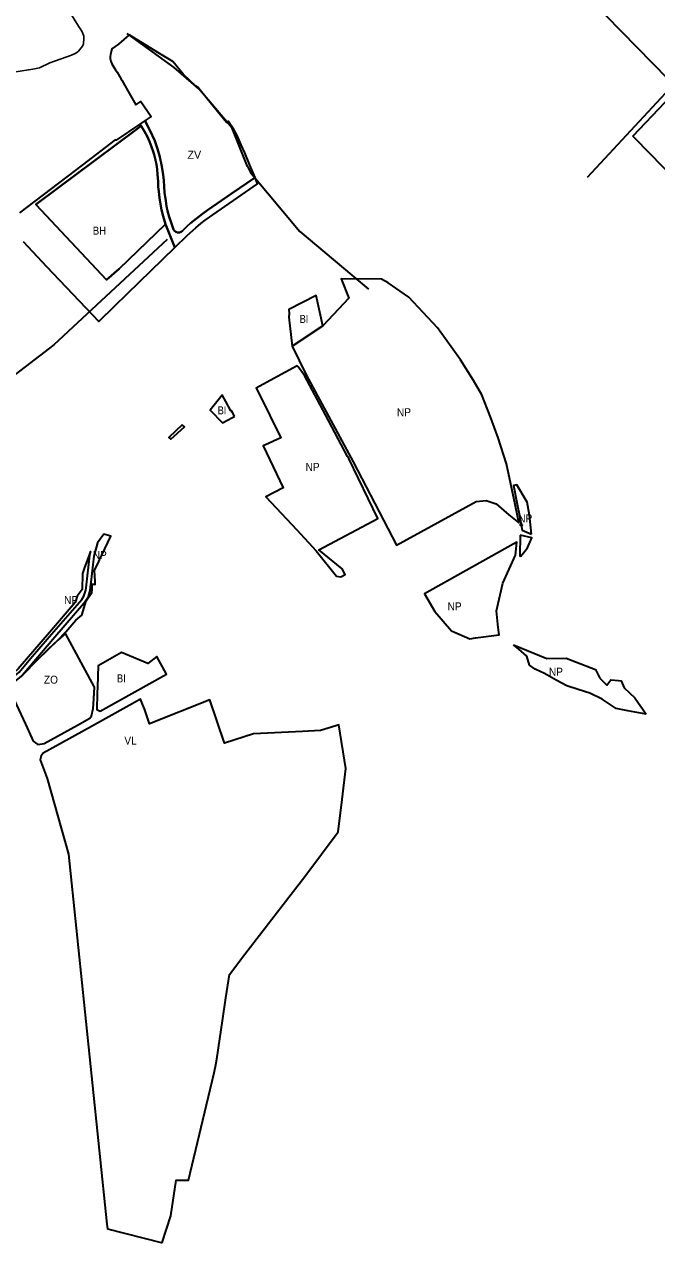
# Model space of a CAD drawing. Extents: x -650276 to -642489, y -1074311 to -1066720.
# Drawn here: x -646730 to -645782, y -1073849 to -1072023 of the extents above; entities that cross this region are included whole.
import ezdxf

# ---------------------------------------------------------------- set-up
doc = ezdxf.new("R2010")
doc.units = 0
doc.header["$LTSCALE"] = 4.8
doc.header["$PDMODE"] = 32
doc.header["$PDSIZE"] = 2.4
for name, color, linetype, lineweight in [('1', 7, 'Continuous', 35), ('15', 7, 'Continuous', 35), ('2', 7, 'Continuous', 35), ('34', 7, 'Continuous', 35), ('40', 7, 'Continuous', 35), ('42', 7, 'Continuous', 35), ('48', 7, 'Continuous', 35), ('54', 7, 'Continuous', 35), ('61', 7, 'Continuous', 25)]:
    doc.layers.add(name, color=color, linetype=linetype, lineweight=lineweight)
doc.layers.add('62', color=7, linetype='Continuous')

msp = doc.modelspace()

# ---------------------------------------------------------------- linework, layer by layer
at = {"layer": '1'}
msp.add_lwpolyline([(-646606.848, -1072405.785), (-646587.666, -1072389.082), (-646518.208, -1072321.92), (-646519.417, -1072318.408), (-646522.007, -1072309.932), (-646524.282, -1072300.849), (-646526, -1072292.201), (-646527.5, -1072282.657), (-646528.566, -1072273.308), (-646529.182, -1072265.941), (-646529.607, -1072258.124), (-646530.188, -1072247.442), (-646530.892, -1072239.747), (-646531.93, -1072232.861), (-646533.286, -1072226.031), (-646535.344, -1072217.844), (-646536.772, -1072213.218), (-646539.168, -1072206.122), (-646539.168, -1072206.122), (-646542.484, -1072197.985), (-646546.09, -1072190.428), (-646549.793, -1072183.38), (-646554.56, -1072175.629), (-646555.051, -1072174.933), (-646563.299, -1072181.091), (-646710.684, -1072291.133), (-646712.634, -1072292.59)], close=True, dxfattribs=at)
at = {"layer": '15'}
msp.add_lwpolyline([(-646529.182, -1072265.941), (-646528.566, -1072273.308), (-646527.5, -1072282.657), (-646526, -1072292.201), (-646524.282, -1072300.849), (-646522.007, -1072309.932), (-646519.417, -1072318.408), (-646518.208, -1072321.92), (-646504.244, -1072357.026), (-646485.656, -1072338.908), (-646473.069, -1072327.765), (-646465.227, -1072321.127), (-646459.03, -1072316.137), (-646380.12, -1072261.44), (-646384.056, -1072252.138), (-646420.085, -1072276.737), (-646455.557, -1072301.131), (-646462.79, -1072306.784), (-646480.923, -1072320.667), (-646486.273, -1072325.526), (-646492.813, -1072332.07), (-646494.794, -1072333.558), (-646497.569, -1072334.55), (-646500.244, -1072334.45), (-646503.018, -1072333.459), (-646504.802, -1072331.971), (-646506.189, -1072329.889), (-646509.954, -1072319.377), (-646512.729, -1072311.048), (-646515.305, -1072301.925), (-646516.692, -1072294.983), (-646518.079, -1072287.051), (-646519.756, -1072274.861), (-646521.051, -1072256.707), (-646521.646, -1072248.378), (-646523.628, -1072235.883), (-646526.798, -1072221.011), (-646530.167, -1072209.31), (-646534.527, -1072197.411), (-646541.822, -1072181.102), (-646547.606, -1072170.835), (-646548.676, -1072166.737), (-646556.693, -1072172.16), (-646555.051, -1072174.933), (-646554.56, -1072175.629), (-646549.793, -1072183.38), (-646546.09, -1072190.428), (-646542.484, -1072197.985), (-646539.168, -1072206.122), (-646536.772, -1072213.218), (-646535.344, -1072217.844), (-646533.286, -1072226.031), (-646531.93, -1072232.861), (-646530.892, -1072239.747), (-646530.188, -1072247.442), (-646529.607, -1072258.124)], close=True, dxfattribs=at)
at = {"layer": '2'}
msp.add_line((-646417.787, -1072612.168), (-646414.77, -1072610.61), dxfattribs=at)
for points in [[(-645817.219, -1072189.975), (-645768.649, -1072139.283), (-645740.45, -1072168.23), (-645559.34, -1072354.42), (-645546.82, -1072365.72), (-645550.41, -1072368.47), (-645636.37, -1072379.57), (-645650.78, -1072342.73), (-645674, -1072338), (-645789.298, -1072218.833)], [(-646333.34, -1072461.67), (-646328.45, -1072504.81), (-646282.47, -1072474.34), (-646292.44, -1072428.89), (-646333.33, -1072450.12), (-646332.68, -1072456.19)], [(-646620.38, -1073015.9), (-646620.71, -1073025.49), (-646621.44, -1073049.79), (-646616.55, -1073052.21), (-646516.7, -1072996.65), (-646531.46, -1072970.12), (-646544.68, -1072980.62), (-646584.23, -1072964.22), (-646619.48, -1072984.34)]]:
    msp.add_lwpolyline(points, close=True, dxfattribs=at)
for points in [[(-646420.36, -1072601.78), (-646427.95, -1072588.07), (-646432.57, -1072579.75), (-646433.36, -1072578.45), (-646451.458, -1072601.008), (-646433.024, -1072620.04), (-646417.787, -1072612.168)], [(-646414.77, -1072610.61), (-646419.11, -1072602.03), (-646419.47, -1072601.31), (-646419.02, -1072604.18), (-646420.36, -1072601.78)]]:
    msp.add_lwpolyline(points, dxfattribs=at)
at = {"layer": '34'}
msp.add_lwpolyline([(-646663.83, -1073266.33), (-646606.251, -1073821.086), (-646605.36, -1073828.11), (-646525.12, -1073848.38), (-646523.34, -1073848.83), (-646510.62, -1073808.79), (-646502.13, -1073755.15), (-646483.76, -1073755.02), (-646446.04, -1073596.49), (-646443.21, -1073584.6), (-646441.43, -1073573.76), (-646436.91, -1073543.35), (-646432.87, -1073516.19), (-646427.79, -1073482.07), (-646422.54, -1073446.74), (-646399.55, -1073416.41), (-646350.34, -1073353.07), (-646309.38, -1073299.93), (-646259.2, -1073233.16), (-646253.35, -1073184.6), (-646247.76, -1073138.19), (-646258.14, -1073072.71), (-646262.94, -1073074.15), (-646285.77, -1073081.01), (-646312.87, -1073082.4), (-646386.27, -1073086.15), (-646430.02, -1073100.1), (-646452.08, -1073034.96), (-646542.62, -1073071.1), (-646550.01, -1073048.55), (-646552.79, -1073041.53), (-646555.79, -1073033.92), (-646624.69, -1073072.66), (-646691.76, -1073109.71), (-646701.78, -1073114.9), (-646704.98, -1073119), (-646706.23, -1073125.02), (-646695.77, -1073153.13)], close=True, dxfattribs=at)
at = {"layer": '40'}
msp.add_lwpolyline([(-646507.28, -1072078.4), (-646530.073, -1072064.559), (-646573.05, -1072038.46), (-646588.75, -1072052.06), (-646598.827, -1072059.244), (-646599.86, -1072063.71), (-646601, -1072067.55), (-646601.42, -1072071.01), (-646601.16, -1072074.07), (-646600.8, -1072075.94), (-646600.22, -1072077.86), (-646598.67, -1072081.55), (-646595.86, -1072086.82), (-646593.13, -1072091.01), (-646591.02, -1072094.4), (-646585.08, -1072104.81), (-646583.9, -1072106.42), (-646577.41, -1072117.76), (-646577.08, -1072118.7), (-646563.11, -1072143.03), (-646555.49, -1072138.17), (-646539.94, -1072160.83), (-646548.676, -1072166.737), (-646547.606, -1072170.835), (-646541.822, -1072181.102), (-646534.527, -1072197.411), (-646530.167, -1072209.31), (-646526.798, -1072221.011), (-646523.628, -1072235.883), (-646521.646, -1072248.378), (-646521.051, -1072256.707), (-646519.756, -1072274.861), (-646518.079, -1072287.051), (-646516.692, -1072294.983), (-646515.305, -1072301.925), (-646512.729, -1072311.048), (-646509.954, -1072319.377), (-646506.189, -1072329.889), (-646504.802, -1072331.971), (-646503.018, -1072333.459), (-646500.244, -1072334.45), (-646497.569, -1072334.55), (-646494.794, -1072333.558), (-646492.813, -1072332.07), (-646486.273, -1072325.526), (-646480.923, -1072320.667), (-646462.79, -1072306.784), (-646455.557, -1072301.131), (-646420.085, -1072276.737), (-646384.056, -1072252.138), (-646391.77, -1072233.91), (-646399.6, -1072215.39), (-646404.67, -1072203.42), (-646410.68, -1072189.36), (-646415.84, -1072180.43), (-646424.56, -1072167.96), (-646426.98, -1072169.74), (-646455.75, -1072134.29), (-646468.35, -1072118.76), (-646469.41, -1072117.44), (-646472.72, -1072115.38), (-646491.69, -1072097.45)], close=True, dxfattribs=at)
at = {"layer": '42'}
msp.add_lwpolyline([(-646731.82, -1072348.2), (-646696.83, -1072385.81), (-646618.158, -1072468.098), (-646594.606, -1072444.422), (-646575.792, -1072426.789), (-646504.244, -1072357.026), (-646518.208, -1072321.92), (-646587.666, -1072389.082), (-646606.848, -1072405.785), (-646712.634, -1072292.59), (-646563.299, -1072181.091), (-646555.051, -1072174.933), (-646556.693, -1072172.16), (-646592.2, -1072196.17), (-646593.85, -1072195.48), (-646643.55, -1072233.5), (-646737.449, -1072305.019)], dxfattribs=at)
msp.add_lwpolyline([(-646668.53, -1072935.52), (-646680.07, -1072945.74), (-646710.3, -1072975.31), (-646732.95, -1072998.07), (-646744.92, -1073007.46), (-646755.58, -1073013.43), (-646728.25, -1073071.54), (-646719.09, -1073092.43), (-646716.98, -1073097.26), (-646709.88, -1073101.87), (-646700.42, -1073100.42), (-646650.54, -1073072.96), (-646631.82, -1073062.65), (-646629.15, -1073059.18), (-646626.91, -1073048.17), (-646626.55, -1073041.48), (-646625.01, -1073016.38)], close=True, dxfattribs=at)
at = {"layer": '48'}
for points in [[(-646056.42, -1072556.49), (-646075.82, -1072525.54), (-646110.61, -1072477.49), (-646153.49, -1072431.54), (-646172.81, -1072418.2), (-646184.449, -1072410.256), (-646194.19, -1072404.62), (-646254.75, -1072404.25), (-646243.17, -1072432.88), (-646282.47, -1072474.34), (-646328.45, -1072504.81), (-646307.6, -1072547.74), (-646236.97, -1072678.31), (-646171.72, -1072803.51), (-646052.58, -1072737.82), (-646037.23, -1072736.38), (-646022.4, -1072741.58), (-646003.22, -1072757.85), (-645988.43, -1072769.93), (-645990.04, -1072761.78), (-645993.89, -1072742.23), (-646006.66, -1072681.4), (-646019.16, -1072642.35), (-646030.17, -1072612.31), (-646043.87, -1072578.12)], [(-646310.01, -1072549.22), (-646319.56, -1072536.05), (-646320.62, -1072534.6), (-646350.18, -1072550.59), (-646382.41, -1072568.01), (-646377.84, -1072576.29), (-646345.6, -1072642.55), (-646368.51, -1072652.81), (-646371.66, -1072654.2), (-646342.08, -1072717.43), (-646367.72, -1072730.68), (-646321.171, -1072780.535), (-646292.17, -1072811.6), (-646261.97, -1072849.66), (-646255.39, -1072850.83), (-646249.04, -1072847.16), (-646253.56, -1072838.8), (-646288.27, -1072810.22), (-646199.72, -1072763.1), (-646243.32, -1072673.57), (-646245.13, -1072670.2), (-646278.44, -1072608.07)], [(-646493.229, -1072622.74), (-646513.209, -1072641.935), (-646510.28, -1072644.42), (-646490.11, -1072626.15)], [(-646644.059, -1072908.208), (-646637.2, -1072886.57), (-646628.7, -1072874.5), (-646628.58, -1072869.88), (-646628.36, -1072861.71), (-646627.159, -1072861.792), (-646625.96, -1072861.874), (-646625.3, -1072861.919), (-646624.824, -1072861.951), (-646623.67, -1072862.024), (-646623.712, -1072861.37), (-646623.95, -1072857.6), (-646625.02, -1072841.21), (-646618.521, -1072827.719), (-646617.407, -1072825.407), (-646614.07, -1072818.47), (-646600.37, -1072790.04), (-646603.99, -1072788.901), (-646610.86, -1072786.74), (-646620.27, -1072799.95), (-646624.54, -1072814.52), (-646625.91, -1072819.66), (-646630.45, -1072858.93), (-646630.57, -1072859.99), (-646630.76, -1072861.61), (-646631.89, -1072871.33), (-646635.11, -1072882.47), (-646640.96, -1072890.83), (-646684.36, -1072941.43), (-646732.95, -1072998.07), (-646710.3, -1072975.31), (-646693.9, -1072958.84), (-646680.07, -1072945.74), (-646668.09, -1072933.43), (-646652.76, -1072915.66), (-646644.069, -1072908.218), (-646644.061, -1072908.209)], [(-645993.47, -1072818.44), (-645991.37, -1072798.84), (-645996.8, -1072801.88), (-646129.91, -1072876.24), (-646114.5, -1072902.8), (-646089.39, -1072931.92), (-646062.04, -1072943.58), (-646053.287, -1072942.399), (-646017.65, -1072937.59), (-646019.21, -1072926.91), (-646021.64, -1072901.6), (-646012.37, -1072860.3)], [(-646642.438, -1072844.29), (-646642.939, -1072845.68), (-646643.574, -1072869.57), (-646650.798, -1072879.828), (-646653.846, -1072889.44), (-646692.432, -1072934.135), (-646739.241, -1072988.798), (-646751.061, -1072999.106), (-646758.883, -1073002.885), (-646760.416, -1073003.25), (-646758.44, -1073007.19), (-646748.51, -1073002.74), (-646737.7, -1072993.52), (-646717.7, -1072969.5), (-646689.13, -1072936.62), (-646644.12, -1072884.84), (-646640.92, -1072879.6), (-646637.92, -1072870.91), (-646637.52, -1072867.43), (-646631.85, -1072818.45), (-646631.08, -1072812.68), (-646640.313, -1072838.394), (-646642.404, -1072844.195), (-646642.39, -1072844.2)]]:
    msp.add_lwpolyline(points, close=True, dxfattribs=at)
for points in [[(-645969.46, -1072787.03), (-645972.31, -1072758.48), (-645975.86, -1072738.61), (-645991.31, -1072712.86), (-645996.31, -1072714.11), (-645990.95, -1072741.65), (-645987.1, -1072761.2), (-645984.79, -1072772.91)], [(-645984.79, -1072772.91), (-645983.22, -1072780.88), (-645969.46, -1072787.03)], [(-645986.24, -1072788.33), (-645986.71, -1072819.26), (-645986.71, -1072819.26)], [(-645975.3, -1072807.37), (-645969.01, -1072792.28), (-645986.24, -1072788.33)], [(-645986.71, -1072819.26), (-645986.71, -1072819.26), (-645985.19, -1072819.72), (-645975.3, -1072807.37)], [(-645972.6, -1072983.41), (-645976.48, -1072969.55), (-645988.49, -1072959.28), (-645996.2, -1072952.69)], [(-645996.2, -1072952.69), (-645946.4, -1072973.05), (-645917.53, -1072972.93), (-645873.3, -1072989.79), (-645866.93, -1073002.72)], [(-645863.39, -1073034.25), (-645882.07, -1073025.22), (-645899.35, -1073019.65), (-645916.47, -1073014.03), (-645932.44, -1073005.5), (-645949.85, -1072995.57), (-645962.81, -1072989.45), (-645963.77, -1072989), (-645972.6, -1072983.41)], [(-645866.93, -1073002.72), (-645858.82, -1073010.74), (-645856.46, -1073013.07), (-645850.37, -1073005.42), (-645838.89, -1073006.18)], [(-645838.89, -1073006.18), (-645834.9, -1073006.45), (-645830.6, -1073016.92), (-645814.27, -1073032.11), (-645797.32, -1073056.62)], [(-645797.32, -1073056.62), (-645824.93, -1073051.83), (-645842.53, -1073048.19), (-645863.39, -1073034.25)]]:
    msp.add_lwpolyline(points, dxfattribs=at)
msp.add_point((-645984.79, -1072772.91), dxfattribs=at)
at = {"layer": '54'}
msp.add_line((-645885.363, -1072251.506), (-645755.385, -1072111.972), dxfattribs=at)
for points in [[(-646336.784, -1071524.232), (-646218.737, -1071612.767), (-646164.374, -1071674.897), (-645904.456, -1071961.331), (-645718.199, -1072151.712), (-645526.944, -1072343.922), (-645538, -1072384), (-645459, -1072440), (-645389, -1072483), (-645335, -1072526), (-645287, -1072569), (-645227, -1072617), (-645139.573, -1072694.628), (-645084.365, -1072788.086)], [(-646395.588, -1072235.707), (-646418.384, -1072178.078), (-646468.581, -1072119.193), (-646505.263, -1072087.337), (-646575.731, -1072036.175)], [(-646395.588, -1072235.707), (-646390.794, -1072244.804), (-646316.998, -1072333.174), (-646213.65, -1072419.58)], [(-646516, -1072345), (-646685.823, -1072502.987), (-646914.429, -1072678.004), (-647018.969, -1072761.795), (-647092.194, -1072861.614), (-647161.068, -1073050.946)]]:
    msp.add_lwpolyline(points, dxfattribs=at)
at = {"layer": '61'}
for points in [[(-646732.05, -1071892.58), (-646721.96, -1071908.47), (-646709.19, -1071928.91), (-646698.88, -1071945.32), (-646665.78, -1071998.02), (-646648.65, -1072025.26), (-646644.03, -1072032.61), (-646642.27, -1072036.3)], [(-646642.27, -1072036.3), (-646640.88, -1072040.43), (-646640.7, -1072041.21), (-646640.73, -1072046.02), (-646640.73, -1072046.02), (-646641.16, -1072049.51)], [(-646641.16, -1072049.51), (-646641.59, -1072051.75), (-646642.05, -1072053.14), (-646643.11, -1072055.41), (-646648.78, -1072062.89), (-646650.1, -1072063.91), (-646653.86, -1072066.41), (-646659.309, -1072068.883), (-646691.77, -1072080.37), (-646707.5, -1072087.64), (-646717.55, -1072090), (-646742.95, -1072093.96)]]:
    msp.add_lwpolyline(points, dxfattribs=at)

# ---------------------------------------------------------------- texts
at = {"layer": '62'}
msp.add_text('ZV', height=12, dxfattribs=at).set_placement((-646485.386, -1072224.148))
for s, width, p in [('BH', 0.9, (-646627.48, -1072337.818)), ('BI', 0.85, (-646317, -1072470.167)), ('BI', 0.85, (-646440, -1072607.167)), ('NP', 0.95, (-646171.335, -1072610.048)), ('NP', 0.95, (-646308.335, -1072692.048)), ('NP', 0.95, (-645989.335, -1072769.048)), ('NP', 0.95, (-646627.575, -1072824.064)), ('NP', 0.95, (-646670.505, -1072891.594)), ('NP', 0.95, (-646095.335, -1072901.048)), ('NP', 0.95, (-645943.335, -1072999.048)), ('ZO', 0.95, (-646700.791, -1073010.902)), ('BI', 0.85, (-646590.991, -1073009.043)), ('VL', 0.95, (-646580.107, -1073102.218))]:
    msp.add_text(s, height=12, dxfattribs=dict(at, width=width)).set_placement(p)

doc.saveas('drawing.dxf')
